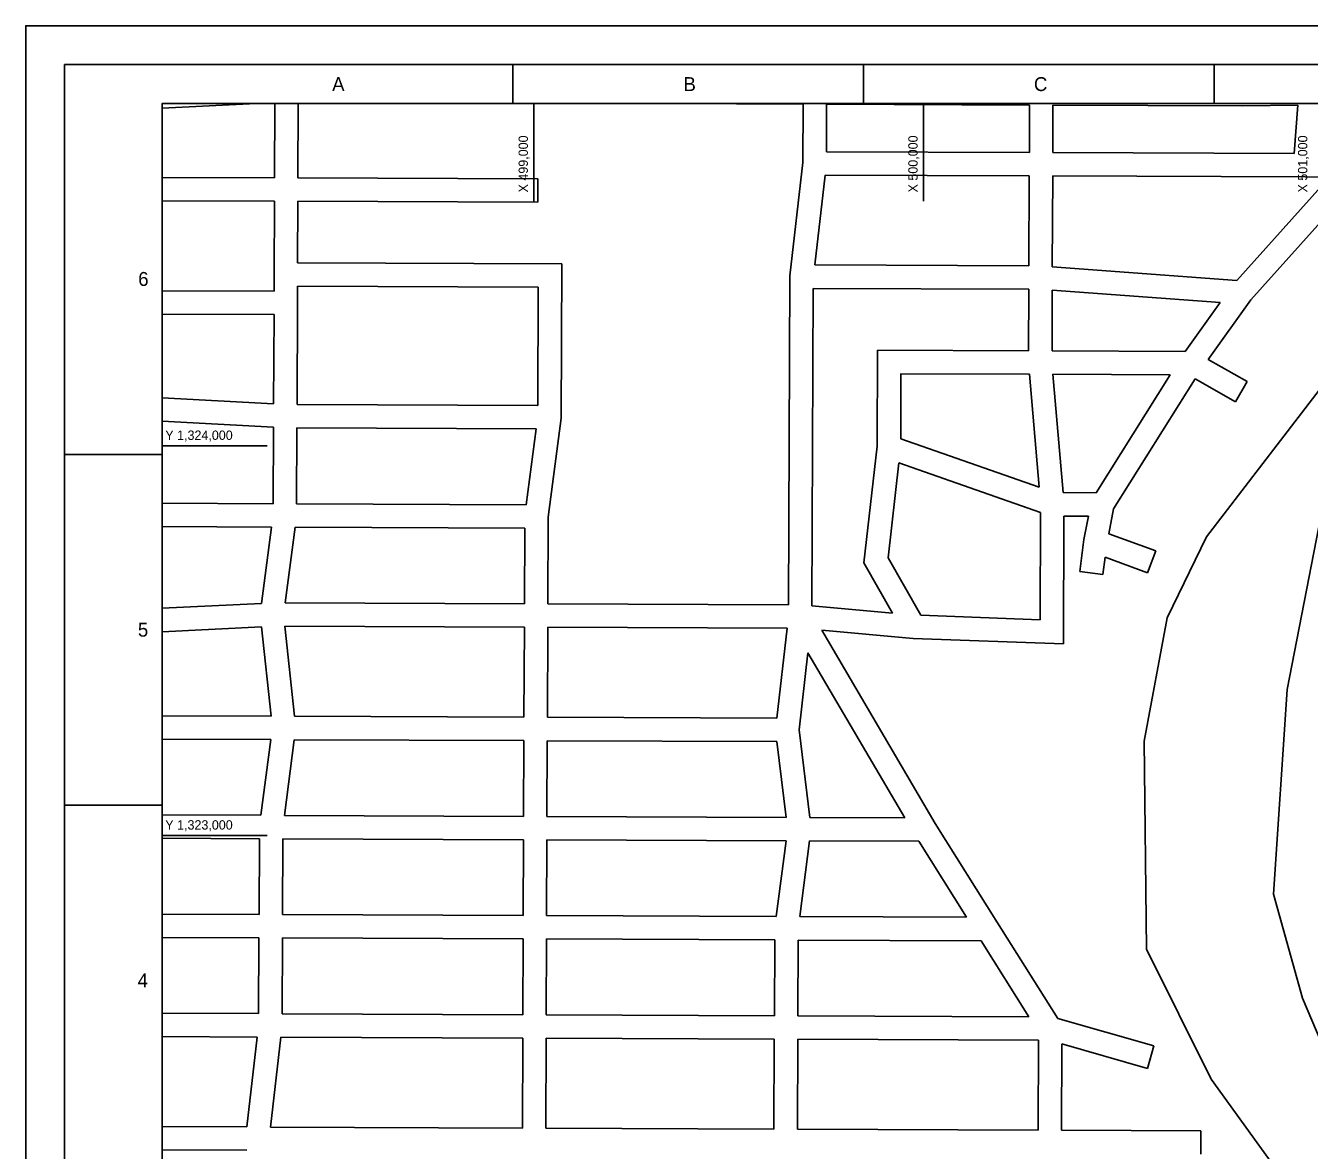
# Model space of a CAD drawing. Extents: x 497696 to 505896, y 1319278 to 1325078.
# Drawn here: x 497696 to 500990, y 1322192 to 1325078 of the extents above; entities that cross this region are included whole.
import ezdxf

# ---------------------------------------------------------------- set-up
doc = ezdxf.new("R2010")
doc.units = 0
for name, color, linetype in [('G-ANNO-TTLB', 7, 'Continuous'), ('Level 1', 7, 'Continuous'), ('Level 2', 7, 'Continuous'), ('Level 3', 7, 'Continuous'), ('Level 32', 7, 'Continuous'), ('Level 5', 7, 'Continuous')]:
    doc.layers.add(name, color=color, linetype=linetype)

msp = doc.modelspace()

# ---------------------------------------------------------------- linework, layer by layer
at = {"layer": 'G-ANNO-TTLB'}
for p, q in [((497796.2, 1324977.9), (497796.2, 1319377.9)), ((505796.2, 1324977.9), (497796.2, 1324977.9)), ((498946.2, 1324877.9), (498946.2, 1324977.9)), ((499846.2, 1324877.9), (499846.2, 1324977.9)), ((500746.2, 1324877.9), (500746.2, 1324977.9)), ((498046.2, 1319477.9), (498046.2, 1324877.9)), ((498046.2, 1324877.9), (505696.2, 1324877.9)), ((498046.2, 1323977.9), (497796.2, 1323977.9)), ((498046.2, 1323077.9), (497796.2, 1323077.9))]:
    msp.add_line(p, q, dxfattribs=at)
for points in [[(497696.2, 1319277.9), (505896.2, 1319277.9), (505896.2, 1325077.9), (497696.2, 1325077.9)], [(497696.2, 1319277.9), (505896.2, 1319277.9), (505896.2, 1325077.9), (497696.2, 1325077.9)], [(497696.2, 1325077.9), (505896.2, 1325077.9), (505896.2, 1319277.9), (497696.2, 1319277.9)]]:
    msp.add_lwpolyline(points, close=True, dxfattribs=at)
msp.add_lwpolyline([(497696.2, 1325027.9), (497696.2, 1325077.9), (497746.2, 1325077.9)], dxfattribs=at)
at = {"layer": 'Level 1'}
for p, q in [((498946.2, 1324877.9), (498946.2, 1324977.9)), ((499846.2, 1324877.9), (499846.2, 1324977.9)), ((500746.2, 1324877.9), (500746.2, 1324977.9)), ((498046.2, 1323977.9), (497796.2, 1323977.9)), ((498046.2, 1323077.9), (497796.2, 1323077.9))]:
    msp.add_line(p, q, dxfattribs=at)
for points in [[(497796.2, 1319377.9), (505796.2, 1319377.9), (505796.2, 1324977.9), (497796.2, 1324977.9)], [(498046.2, 1319477.9), (505696.2, 1319477.9), (505696.2, 1324877.9), (498046.2, 1324877.9)]]:
    msp.add_lwpolyline(points, close=True, dxfattribs=at)
at = {"layer": 'Level 2'}
for p, q in [((499000, 1324627.9), (499000, 1324877.9)), ((500000, 1324627.9), (500000, 1324877.9)), ((498046.2, 1324000), (498316.2, 1324000)), ((498046.2, 1323000), (498316.2, 1323000))]:
    msp.add_line(p, q, dxfattribs=at)
at = {"layer": 'Level 32'}
for p, q in [((498287.7, 1324877.9), (498046.2, 1324865.9)), ((498334.9, 1324687.5), (498335.6, 1324877.9)), ((498394.9, 1324687.2), (498395.6, 1324877.9)), ((499691.3, 1324876.5), (499348.3, 1324877.9)), ((499690.7, 1324726.4), (499691.3, 1324876.5)), ((499750.8, 1324754.5), (499751.3, 1324876.3)), ((500272.3, 1324874.3), (499751.3, 1324876.3)), ((500271.8, 1324752.5), (500272.3, 1324874.3)), ((500331.8, 1324752.2), (500332.3, 1324874)), ((500819.2, 1324872.1), (500332.3, 1324874)), ((500819.2, 1324872.1), (500960.8, 1324873.9)), ((500951.6, 1324749.8), (500960.8, 1324873.9)), ((500271.8, 1324752.5), (499750.8, 1324754.5)), ((500951.6, 1324749.8), (500331.8, 1324752.2)), ((499657.3, 1324435.7), (499690.7, 1324726.4)), ((498334.9, 1324687.5), (498046.2, 1324688.6)), ((499010.4, 1324684.8), (498394.9, 1324687.2)), ((499010.2, 1324624.8), (499010.4, 1324684.8)), ((499720.9, 1324463.8), (499747.4, 1324694.5)), ((500271.5, 1324692.5), (499747.4, 1324694.5)), ((500270.6, 1324461.6), (500271.5, 1324692.5)), ((500330.6, 1324459.4), (500331.5, 1324692.2)), ((500979.4, 1324689.7), (500331.5, 1324692.2)), ((500804.3, 1324424.1), (501041.7, 1324689.4)), ((500840.2, 1324374.3), (501130.9, 1324699.2)), ((501041.7, 1324689.4), (500979.4, 1324689.7)), ((498334.6, 1324627.5), (498046.2, 1324628.6)), ((498333.9, 1324439.3), (498334.6, 1324627.5)), ((498394, 1324469.1), (498394.6, 1324627.2)), ((499010.2, 1324624.8), (498394.6, 1324627.2)), ((498333.7, 1324396.6), (498333.9, 1324439.3)), ((499071.8, 1324466.4), (498394, 1324469.1)), ((499070.2, 1324070.9), (499071.8, 1324466.4)), ((500270.6, 1324461.6), (499720.9, 1324463.8)), ((500804.3, 1324424.1), (500330.6, 1324459.4)), ((498393.6, 1324366.4), (498393.8, 1324409.1)), ((499011.6, 1324406.6), (498393.8, 1324409.1)), ((499010.4, 1324103.1), (499011.6, 1324406.6)), ((499653.9, 1323591.5), (499657.3, 1324435.7)), ((498333.7, 1324396.6), (498046.2, 1324397.8)), ((499713.9, 1323588.9), (499717.1, 1324403.8)), ((500270.4, 1324401.6), (499717.1, 1324403.8)), ((500269.8, 1324243.5), (500270.4, 1324401.6)), ((500329.8, 1324243.3), (500330.4, 1324399.2)), ((500761.3, 1324367.2), (500330.4, 1324399.2)), ((500730.8, 1324221.5), (500840.2, 1324374.3)), ((498392.5, 1324105.5), (498393.6, 1324366.4)), ((500671.6, 1324241.9), (500761.3, 1324367.2)), ((498333.5, 1324336.6), (498046.2, 1324337.8)), ((498332.5, 1324107.3), (498333.5, 1324336.6)), ((500671.6, 1324241.9), (500329.8, 1324243.3)), ((500830.6, 1324164.7), (500730.8, 1324221.5)), ((500296.7, 1323893.4), (500272.1, 1324183.5)), ((500358.1, 1323879.6), (500332.3, 1324183.3)), ((500632.9, 1324182.1), (500332.3, 1324183.3)), ((500443, 1323879.3), (500632.9, 1324182.1)), ((500488, 1323838), (500697.1, 1324171.6)), ((500801, 1324112.6), (500697.1, 1324171.6)), ((500801, 1324112.6), (500830.6, 1324164.7)), ((498332.5, 1324107.3), (498046.2, 1324123.2)), ((499010.4, 1324103.1), (498392.5, 1324105.5)), ((498332.3, 1324047.3), (498046.2, 1324063.1)), ((498331.5, 1323851.3), (498332.3, 1324047.3)), ((498391.5, 1323851), (498392.3, 1324045.5)), ((499006.1, 1324043.1), (498392.3, 1324045.5)), ((498980.6, 1323848.7), (499006.1, 1324043.1)), ((499037, 1323816.6), (499070.2, 1324070.9)), ((500296.7, 1323893.4), (499941.5, 1324018)), ((500300.4, 1323828.5), (499937, 1323956)), ((500443, 1323879.3), (500358.1, 1323879.6)), ((498331.5, 1323851.3), (498046.2, 1323852.4)), ((498980.6, 1323848.7), (498391.5, 1323851)), ((499036.1, 1323594), (499037, 1323816.6)), ((500299.3, 1323553.6), (500300.4, 1323828.5)), ((500359.1, 1323491.4), (500360.4, 1323819.6)), ((500423.2, 1323819.3), (500360.4, 1323819.6)), ((500423.2, 1323819.3), (500411.5, 1323759.6)), ((500488, 1323838), (500475.5, 1323774.1)), ((498327.2, 1323791.3), (498046.2, 1323792.4)), ((498301.6, 1323595.5), (498327.2, 1323791.3)), ((498362.3, 1323596.7), (498387.7, 1323791.1)), ((498976.8, 1323788.7), (498387.7, 1323791.1)), ((498976.1, 1323594.2), (498976.8, 1323788.7)), ((500411.5, 1323759.6), (500400.8, 1323677.2)), ((500475.5, 1323774.1), (500595.9, 1323730)), ((500466, 1323713.7), (500460.2, 1323669.5)), ((500466, 1323713.7), (500575.2, 1323673.7)), ((500595.9, 1323730), (500575.2, 1323673.7)), ((500460.2, 1323669.5), (500400.8, 1323677.2)), ((498301.6, 1323595.5), (498046.2, 1323582.9)), ((498976.1, 1323594.2), (498362.3, 1323596.7)), ((499653.9, 1323591.5), (499036.1, 1323594)), ((499920.9, 1323570.5), (499713.9, 1323588.9)), ((500299.3, 1323553.6), (499993.2, 1323564.9)), ((498301.3, 1323535.4), (498046.2, 1323522.8)), ((498325.8, 1323306), (498301.3, 1323535.4)), ((498386.2, 1323305.7), (498361.5, 1323536.7)), ((498975.8, 1323534.2), (498361.5, 1323536.7)), ((498974.9, 1323303.4), (498975.8, 1323534.2)), ((499034.9, 1323303.1), (499035.8, 1323534)), ((499650.2, 1323531.6), (499035.8, 1323534)), ((499623.6, 1323300.8), (499650.2, 1323531.6)), ((499973.6, 1323505.6), (499739.1, 1323526.4)), ((500030, 1323030.4), (499739.1, 1323526.4)), ((500359.1, 1323491.4), (499973.6, 1323505.6)), ((499680.6, 1323270.8), (499703.3, 1323468.8)), ((499951.9, 1323045), (499703.3, 1323468.8)), ((498325.8, 1323306), (498046.2, 1323307.1)), ((498974.9, 1323303.4), (498386.2, 1323305.7)), ((499623.6, 1323300.8), (499034.9, 1323303.1)), ((499708.2, 1323046), (499680.6, 1323270.8)), ((498325.1, 1323246), (498046.2, 1323247.1)), ((498299.6, 1323051.6), (498325.1, 1323246)), ((498360.1, 1323051.3), (498385.5, 1323245.7)), ((498974.7, 1323243.4), (498385.5, 1323245.7)), ((498973.9, 1323048.9), (498974.7, 1323243.4)), ((499033.9, 1323048.7), (499034.7, 1323243.1)), ((499623.8, 1323240.8), (499034.7, 1323243.1)), ((499647.7, 1323046.2), (499623.8, 1323240.8)), ((498299.6, 1323051.6), (498046.2, 1323052.6)), ((498973.9, 1323048.9), (498360.1, 1323051.3)), ((499647.7, 1323046.2), (499033.9, 1323048.7)), ((499951.9, 1323045), (499708.2, 1323046)), ((500190.2, 1322775.7), (500030, 1323030.4)), ((498295.8, 1322991.6), (498046.2, 1322992.6)), ((498295, 1322797.1), (498295.8, 1322991.6)), ((498355, 1322796.9), (498355.8, 1322991.4)), ((498973.7, 1322988.9), (498355.8, 1322991.4)), ((498972.9, 1322794.4), (498973.7, 1322988.9)), ((499032.9, 1322794.2), (499033.7, 1322988.7)), ((499647.5, 1322986.2), (499033.7, 1322988.7)), ((499622, 1322791.8), (499647.5, 1322986.2)), ((499682.5, 1322791.6), (499707.9, 1322986)), ((499987.8, 1322984.9), (499707.9, 1322986)), ((500110.4, 1322789.9), (499987.8, 1322984.9)), ((498295, 1322797.1), (498046.2, 1322798.1)), ((498972.9, 1322794.4), (498355, 1322796.9)), ((499622, 1322791.8), (499032.9, 1322794.2)), ((500110.4, 1322789.9), (499682.5, 1322791.6)), ((500344.5, 1322530.3), (500190.2, 1322775.7)), ((498294.8, 1322737.1), (498046.2, 1322738.1)), ((498294, 1322542.6), (498294.8, 1322737.1)), ((498354, 1322542.4), (498354.8, 1322736.9)), ((498972.6, 1322734.4), (498354.8, 1322736.9)), ((498971.9, 1322539.9), (498972.6, 1322734.4)), ((499031.9, 1322539.7), (499032.6, 1322734.2)), ((499618.2, 1322731.8), (499032.6, 1322734.2)), ((499617.4, 1322537.4), (499618.2, 1322731.8)), ((499677.4, 1322537.1), (499678.2, 1322731.6)), ((500148.2, 1322729.8), (499678.2, 1322731.6)), ((500270.7, 1322534.8), (500148.2, 1322729.8)), ((498294, 1322542.6), (498046.2, 1322543.6)), ((498971.9, 1322539.9), (498354, 1322542.4)), ((499617.4, 1322537.4), (499031.9, 1322539.7)), ((500270.7, 1322534.8), (499677.4, 1322537.1)), ((500591.4, 1322459.7), (500344.5, 1322530.3)), ((498290.3, 1322482.6), (498046.2, 1322483.6)), ((498263.7, 1322251.9), (498290.3, 1322482.6)), ((498324.1, 1322251.7), (498350.6, 1322482.4)), ((498971.6, 1322479.9), (498350.6, 1322482.4)), ((498970.7, 1322249.1), (498971.6, 1322479.9)), ((499030.7, 1322248.8), (499031.6, 1322479.7)), ((499617.2, 1322477.4), (499031.6, 1322479.7)), ((499616.3, 1322246.5), (499617.2, 1322477.4)), ((499676.3, 1322246.3), (499677.2, 1322477.1)), ((500295.1, 1322474.7), (499677.2, 1322477.1)), ((500294.1, 1322243.8), (500295.1, 1322474.7)), ((500354.1, 1322243.6), (500355, 1322464.8)), ((500574.9, 1322402), (500355, 1322464.8)), ((500574.9, 1322402), (500591.4, 1322459.7)), ((498263.7, 1322251.9), (498046.2, 1322252.8)), ((498970.7, 1322249.1), (498324.1, 1322251.7)), ((499616.3, 1322246.5), (499030.7, 1322248.8)), ((500294.1, 1322243.8), (499676.3, 1322246.3)), ((500711.5, 1322242.2), (500354.1, 1322243.6)), ((500711.3, 1322182.2), (500711.5, 1322242.2)), ((498263.9, 1322191.9), (498046.2, 1322192.8))]:
    msp.add_line(p, q, dxfattribs=at)
for points in [[(500269.8, 1324243.5), (499882.4, 1324245), (499881.5, 1323998.6)], [(500272.1, 1324183.5), (499942.2, 1324184.8), (499941.5, 1324018)], [(499881.5, 1323998.6), (499847.1, 1323699.7), (499920.9, 1323570.5)], [(499937, 1323956), (499909, 1323712.4), (499993.2, 1323564.9)]]:
    msp.add_lwpolyline(points, dxfattribs=at)
at = {"layer": 'Level 5'}
for points in [[(501677.2, 1324877.9), (501378.4, 1324614.6), (500725.8, 1323766.4), (500625.2, 1323558.4), (500565.9, 1323241.9), (500572.6, 1322708.4), (500738.3, 1322374.6), (500985.2, 1322032), (501020.7, 1321975.5), (501090.8, 1321884.7), (501394.4, 1321835.2), (501726.7, 1321794.1), (502293.5, 1321269.9), (502409.4, 1320994.5), (502987.7, 1320510.5), (503056.9, 1320142.4), (503189.4, 1319858.7), (503438.4, 1319516.2), (503472.5, 1319477.9)], [(504107.7, 1319477.9), (503822.6, 1319798.4), (503531.7, 1320041), (503232.9, 1320458.6), (503199.8, 1320550.4), (502737.7, 1321243.7), (502440.6, 1321661.5), (502255.8, 1321845.1), (502052.9, 1321934.2), (501254.5, 1322198), (501046.8, 1322407), (500972.3, 1322582.2), (500898.1, 1322849.2), (500933, 1323374.1), (501045.4, 1323950.4), (501078.5, 1324015.1), (501460.9, 1324322.7), (501588.1, 1324548.9), (501884.4, 1324877.9)]]:
    msp.add_lwpolyline(points, dxfattribs=at)

# ---------------------------------------------------------------- texts
at = {"layer": 'G-ANNO-TTLB'}
for s, p in [('A', (498482.6, 1324910.1)), ('B', (499384.2, 1324910.1)), ('C', (500283.4, 1324910.1)), ('6', (497985, 1324410.1)), ('5', (497984.2, 1323510.1)), ('4', (497983.4, 1322610.1))]:
    msp.add_text(s, height=35.7, dxfattribs=at).set_placement(p)
at = {"layer": 'Level 3'}
for s, p in [('X 499,000', (498985, 1324649.9)), ('X 500,000', (499985, 1324649.9)), ('X 501,000', (500985, 1324649.9))]:
    msp.add_text(s, height=24, rotation=90, dxfattribs=at).set_placement(p)
for s, p in [('Y 1,324,000', (498054.4, 1324015)), ('Y 1,323,000', (498054.4, 1323015))]:
    msp.add_text(s, height=24, dxfattribs=at).set_placement(p)

doc.saveas('drawing.dxf')
